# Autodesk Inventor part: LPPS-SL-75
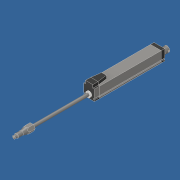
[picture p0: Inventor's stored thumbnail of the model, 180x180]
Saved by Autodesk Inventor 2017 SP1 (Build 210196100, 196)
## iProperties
Created: 2016-12
Part Number: LPPS-SL-75
Material: Stainless Steel
Document SubType Name: Modeling
Designer: JN
Density: 8 g/cm^3
Appearance: Stainless - Brushed
Author: JN
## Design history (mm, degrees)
sketch "Sketch1"
  geometry: C1 r 2.54 at (0, 0)
  constraints: 1 centre point, 1 other
  dimensions: "d0" = 5.08 diameter of C1
extrude "Extrusion1" new body sketch "Sketch1" distance "d1" = 4.572; taper "d2" = 0 deg
sketch "Sketch2"
  geometry: C1 r 3.48 at (0, 0)
  constraints: 1 centre point
  dimensions: "d3" = 6.9596 diameter of C1
extrude "Extrusion2" join sketch "Sketch2" distance "d4" = 8.2042; taper "d5" = 0 deg
workaxis "Work Axis1"
revolve "Revolution2" stored, may be unused: angle "d8" = 90 deg
sketch "Sketch7"
  geometry: L1 (-5.778, 0)-(-2.889, 5.004); L2 (-2.889, 5.004)-(2.889, 5.004); L3 (2.889, 5.004)-(5.778, 0); L4 (5.778, 0)-(2.889, -5.004); L5 (2.889, -5.004)-(-2.889, -5.004); L6 (-2.889, -5.004)-(-5.778, 0); L7 (0, 0)-(0, 8.469); L8 (-0.303, -0.272)-(8.166, -0.272); L9 (0, -3.48)-(0, 0)
  constraints: 18 end point, 3 perpendicular, 1 horizontal, 1 vertical alignment, 14 other
  dimensions: "d20" = 90 deg angle of L8 L7; "d23" = 10.0076 distance between parallel lines of L5 L2
extrude "Extrusion4" join sketch "Sketch7" distance "d21" = 18.03974; taper "d22" = 0 deg
sketch "Sketch8"
  geometry: L1 (3.48, -4.572)-(3.48, -12.776) reference; L2 (0, 1.416)-(0, -21.685); L3 (0, -12.776)-(0, -30.816) reference; L4 (0, 9.356)-(0, -46.226) reference; L5 (5.004, -30.816)-(-5.004, -30.816); L6 (5.004, -30.816)-(0, -30.816) reference; L7 (0, -30.816)-(-5.004, -30.816) reference; L8 (-5.004, -12.776)-(-5.004, -30.816) reference; L9 (-5.004, -30.816)-(-5.004, -12.776); L10 (4.859, -30.943)-(-0.272, -30.943); L11 (-3.48, -12.776)-(3.48, -12.776) reference; L12 (3.48, -4.572)-(3.48, -12.776) reference; L13 (3.48, -12.776)-(3.481, -12.776); L14 (3.481, -12.776)-(9.456, -38.286); L15 (3.481, -12.776)-(9.456, -12.776); L16 (9.456, -38.286)-(9.456, -12.776); A1 r 1.416 centre (0, 0) between (1.416, 0) and (-1.416, 0) reference; 1 further point
  constraints: 16 end point, 2 collinear, 1 horizontal, 1 perpendicular, 1 point on circle, 1 point on line, 1 vertical
revolve "Revolution9" sketch "Sketch8" stored, may be unused: angle "d35" = 90 deg
sketch "Sketch9"
  geometry: C1 r 2.54 at (0, 0)
  constraints: 1 centre point
  dimensions: "d36" = 5.08 diameter of C1
extrude "Extrusion5" join sketch "Sketch9" distance "d37" = 96.52 (= Stroke); taper "d38" = 0 deg
sketch "Sketch10"
  geometry: C1 r 2.54 at (0, 0) reference; C2 r 4.521 at (0, 0)
  constraints: 1 centre point, 1 coincident
  dimensions: "d39" = 9.0424 diameter of C2
extrude "Extrusion6" join sketch "Sketch10" distance "d40" = 2; taper "d41" = 0 deg
sketch "Sketch11"
  geometry: L1 (-9.143, 16.927)-(9.145, 16.927); L2 (9.145, -6.949)-(-9.143, -6.949); L3 (-9.143, -6.949)-(-9.143, 16.927); L4 (-5.778, 0)-(-2.889, -5.004) reference; L5 (5.778, 0)-(2.889, 5.004) reference; L6 (-5.778, 0)-(5.778, 0); L7 (2.889, 5.004)-(-2.889, 5.004) reference; L8 (0, 5.004)-(0, -5.004); L9 (-2.889, -5.004)-(2.889, -5.004) reference; L10 (9.145, -6.949)-(9.145, -4.663); L11 (9.145, -4.663)-(7.621, -4.663); L12 (7.621, -4.663)-(7.621, -2.377); L13 (7.621, -2.377)-(9.145, -2.377); L14 (9.145, 16.927)-(9.145, -2.377); L15 (9.145, -4.663)-(9.145, -6.949); L16 (-9.143, -2.377)-(-7.619, -2.377); L17 (-7.619, -2.377)-(-7.619, -4.663); L18 (-7.619, -4.663)-(-9.143, -4.663)
  constraints: 28 end point, 9 perpendicular, 4 parallel, 4 point on line, 2 horizontal, 2 midpoint
  dimensions: "d42" = 18.288 distance of L1.start L1.end; "d43" = 3.3655 distance from line of L3 L4.start; "d47" = 23.876 distance of L1.end L2.start; "d49" = 1.94564 distance between parallel lines of L2 L9; "d98" = 2.286 distance of L2.start L10.end; "d99" = 1.524 distance of L10.end L11.end; "d100" = 2.286 distance of L11.end L12.end; "d101" = 1.524 distance of L16.start L16.end
extrude "Extrusion7" join sketch "Sketch11" distance "d50" = 9; taper "d51" = 0 deg
sketch "Sketch12"
  geometry: L1 (-9.145, -6.949)-(-9.145, 16.927) reference; L2 (9.143, 16.927)-(9.143, -6.949) reference; L3 (9.143, -6.949)-(-9.145, -6.949) reference; L4 (-9.145, -6.949)-(9.143, -6.949); L5 (-9.145, 16.927)-(9.143, 16.927); L6 (-9.145, 16.927)-(-9.145, -6.949); L7 (-9.145, 16.927)-(9.143, 16.927) reference; L8 (-6.319, 16.927)-(-6.319, 11.593); L9 (6.318, 16.927)-(6.318, 11.593); L10 (-9.145, 11.593)-(-6.319, 11.593); L11 (6.318, 11.593)-(9.143, 11.593)
  constraints: 15 end point, 4 parallel, 2 perpendicular, 2 point on line, 1 collinear
  dimensions: "d52" = 23.876 distance between parallel lines of L4 L5; "d55" = 2.82575 distance between parallel lines of L8 L1; "d56" = 2.82575 distance between parallel lines of L9 L2; "d57" = 18.542 distance between parallel lines of L3 L10; "d58" = 18.542 distance between parallel lines of L3 L11
extrude "Extrusion8" cut sketch "Sketch12" distance "d59" = 9; taper "d60" = 0 deg
mirror "Mirror1"
sketch "Sketch13"
  geometry: L1 (9.145, 11.593)-(6.319, 11.593) reference; L2 (-6.319, 16.927)-(6.319, 16.927); L3 (6.319, 16.927)-(6.319, 11.593); L4 (6.319, 11.593)-(-6.319, 11.593); L5 (-6.319, 11.593)-(-6.319, 16.927)
  constraints: 8 end point, 2 parallel, 1 horizontal, 1 perpendicular
workplane "Work Plane1"
sketch "Sketch14"
  geometry: L1 (6.319, 16.927)-(-6.319, 16.927) reference; L2 (-4.109, 16.927)-(4.121, 16.927); L3 (4.121, 16.927)-(4.121, 11.558); L4 (4.121, 11.558)-(-4.109, 11.558); L5 (-4.109, 11.558)-(-4.109, 16.927); L6 (-6.319, 16.927)-(-6.319, 11.593) reference; L7 (6.319, 11.593)-(6.319, 16.927) reference; 1 further point
  constraints: 8 end point, 2 parallel, 2 perpendicular, 1 horizontal, 1 point on line
  dimensions: "d62" = 8.2296 distance of L3.end L4.end; "d63" = 2.2098 distance between parallel lines of L6 L5; "d65" = 2.6844 distance from line of point (0.006, 14.242) L1; "d66" = 4.1148 distance from line of L5 point (0.006, 14.242)
sketch "3D Sketch1"
loft "Loft1" sketch "3D Sketch1" dims "d67" = 0, "d68" = 90 deg, "d69" = 0, "d70" = 90 deg, "d71" = 0, "d72" = 90 deg
sketch "Sketch15"
  geometry: L1 (-6.319, 11.593)-(-9.143, 11.593) reference; L2 (9.145, -6.949)-(9.145, 11.593) reference; L3 (-9.143, 11.593)-(9.145, 11.593); L4 (9.145, -6.949)-(-9.143, -6.949); L5 (7.621, -2.377)-(9.145, -2.377) reference; L6 (9.145, -2.377)-(7.621, -2.377); L7 (7.621, -4.663)-(7.621, -2.377) reference; L8 (7.621, -2.377)-(7.621, -4.663); L9 (9.145, -4.663)-(7.621, -4.663) reference; L10 (7.621, -4.663)-(9.145, -4.663); L11 (-9.143, -2.377)-(-7.619, -2.377) reference; L12 (-7.619, -4.663)-(-9.143, -4.663) reference; L13 (-9.143, -4.663)-(-7.619, -4.663); L14 (-7.619, -2.377)-(-7.619, -4.663) reference; L15 (-7.619, -4.663)-(-7.619, -2.377); L16 (-9.143, 11.593)-(-9.143, -2.377) reference; L17 (-7.619, -2.377)-(-9.143, -2.377); L18 (9.145, 11.593)-(9.145, -2.377); L19 (9.145, -4.663)-(9.145, -6.949); L20 (-9.143, -6.949)-(-9.143, -4.663); L21 (-9.143, -2.377)-(-9.143, 11.593)
  constraints: 24 end point, 5 parallel, 5 perpendicular, 3 collinear, 1 horizontal
extrude "Extrusion9" new body sketch "Sketch15" distance "d73" = 105.6386 (= Body); taper "d74" = 0 deg
sketch "Sketch16"
  geometry: L1 (-9.143, 11.593)-(-9.143, -6.949) reference; L2 (-9.143, -6.949)-(9.145, -6.949) reference; L3 (-9.143, 11.593)-(9.145, 11.593); L4 (9.145, -6.949)-(-9.143, -6.949); L5 (7.621, -2.377)-(9.145, -2.377) reference; L6 (9.145, -2.377)-(7.621, -2.377); L7 (9.145, -4.663)-(7.621, -4.663) reference; L8 (7.621, -2.377)-(7.621, -4.663); L9 (7.621, -4.663)-(9.145, -4.663); L10 (-9.143, -2.377)-(-7.619, -2.377) reference; L11 (-9.143, -2.377)-(-7.619, -2.377); L12 (-7.619, -2.377)-(-7.619, -4.663) reference; L13 (-7.619, -2.377)-(-7.619, -4.663); L14 (-7.619, -4.663)-(-9.143, -4.663) reference; L15 (-7.619, -4.663)-(-9.143, -4.663); L16 (-9.143, -6.949)-(-9.143, -4.663); L17 (-9.143, -2.377)-(-9.143, 11.593); L18 (9.145, 11.593)-(9.145, -2.377); L19 (9.145, -4.663)-(9.145, -6.949)
  constraints: 24 end point, 5 parallel, 4 perpendicular, 3 collinear, 2 horizontal
extrude "Extrusion10" new body sketch "Sketch16" distance "d75" = 6.0071; taper "d76" = 0 deg
sketch "Sketch17"
  geometry: L1 (-9.143, 11.593)-(9.145, 11.593) reference; L2 (9.145, 11.593)-(9.145, -2.377) reference; L3 (9.145, -6.949)-(-9.143, -6.949) reference; L4 (-9.143, -6.949)-(-9.143, -4.663) reference; L5 (-9.143, -4.663)-(-7.619, -4.663) reference; L6 (-7.619, -4.663)-(-7.619, -2.377) reference; L7 (-7.619, -2.377)-(-9.143, -2.377) reference; L8 (-9.143, -2.377)-(-9.143, 11.593) reference; L9 (9.145, -2.377)-(7.621, -2.377) reference; L10 (7.621, -2.377)-(7.621, -4.663) reference; L11 (7.621, -4.663)-(9.145, -4.663) reference; L12 (9.145, -4.663)-(9.145, -6.949) reference; C1 r 2.54 at (0, 0) reference; C2 r 1.416 at (0, 0) reference; C3 r 4.051 at (0, 0)
  constraints: 1 centre point, 1 coincident
  dimensions: "d77" = 8.1026 diameter of C3
extrude "Extrusion11" new body sketch "Sketch17" distance "d78" = 5; taper "d79" = 0 deg
sketch "Sketch18"
  geometry: C1 r 1.416 at (0, 0) reference; C2 r 5 at (0, 0)
  constraints: 1 centre point, 1 coincident
  dimensions: "d80" = 10 diameter of C2
extrude "Extrusion12" new body sketch "Sketch18" distance "d81" = 8; taper "d82" = 0 deg
shell "Shell2" dims "d84" = 1.397
workaxis "Work Axis4"
workplane "Work Plane2"
sketch "Sketch19"
  geometry: L1 (-5, -8)-(5, -8) reference; L2 (0, -8)-(0, -6.095); 1 further point
  constraints: 2 end point, 1 coincident, 1 midpoint, 1 vertical
  dimensions: "d85" = 1.905 distance of L2.start L2.end
hole "Hole1" sketch "Sketch19" at (0, -6.095) diameter "d86" = 2.3876; stored, may be unused: countersink angle "d90" = 82 deg, drill point angle "d92" = 118 deg; dims "d87" = 19.05, "d88" = 9.525, "d89" = 6.35, "d91" = 25.4
body "Solid1"
sketch "Sketch3"
  geometry: L1 (-2.54, 0)-(2.54, 0) reference; L2 (1.416, 0)-(0, 0); L3 (0, 0)-(0, 1.416); A1 r 1.416 centre (0, 0) between (1.416, 0) and (0, 1.416)
  constraints: 4 end point, 2 point on circle, 1 centre point, 1 midpoint, 1 vertical
  dimensions: "d6" = 2.8321 diameter of A1
body "Solid2"
body "Solid3"
body "Solid4"
body "Solid5"
node "Project Cut Edges1"
other parameters: "Stroke" = 96.52 [user parameter; used in 1 equation term], "Body" = 105.6386 [user parameter; used in 1 equation term], "d53" = 5.334, "d61" = 16.51
